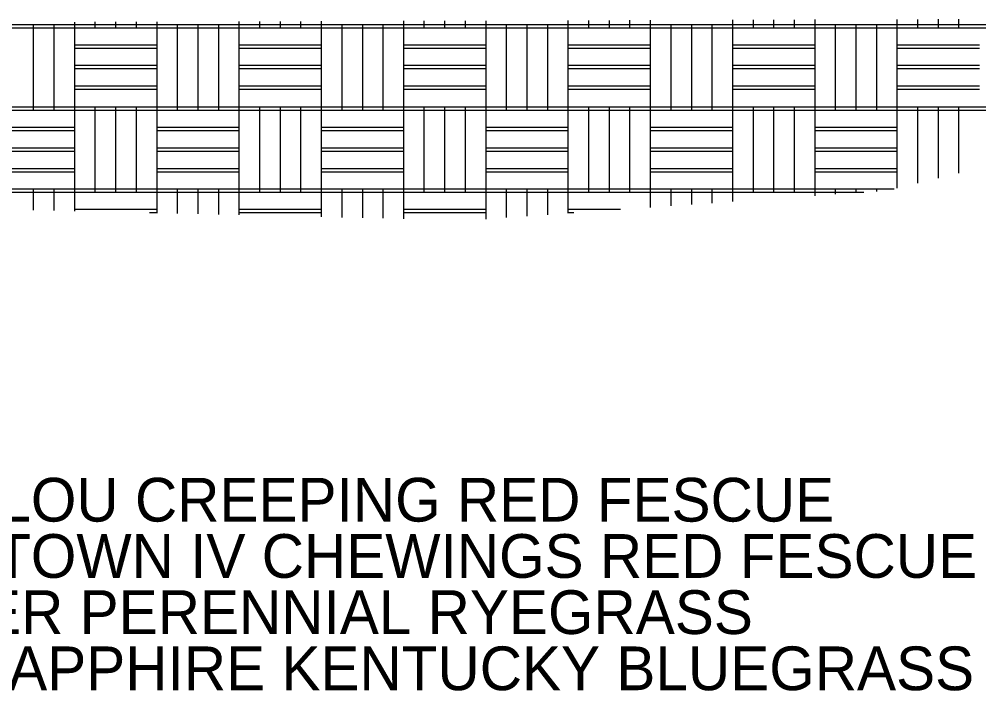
# Model space of a CAD drawing. Extents: x 9915.7 to 9955.7, y 9888.6 to 9936.3.
# Drawn here: x 9926.81 to 9942.16, y 9912.72 to 9923.46 of the extents above; entities that cross this region are included whole.
import ezdxf

# ---------------------------------------------------------------- set-up
doc = ezdxf.new("R2010")
doc.units = 0
for name, color, linetype in [('Default', 7, 'Continuous'), ('G-ANNO-TEXT', 7, 'Continuous'), ('G-DETL-PATT', 7, 'Continuous')]:
    doc.layers.add(name, color=color, linetype=linetype)

msp = doc.modelspace()

# ---------------------------------------------------------------- linework, layer by layer
at = {"layer": 'Default'}
for p, q in [((9936.91, 9923.05), (9935.594, 9923.05)), ((9939.541, 9923.05), (9938.225, 9923.05)), ((9942.172, 9923.05), (9940.856, 9923.05)), ((9935.684, 9920.366), (9935.594, 9920.366))]:
    msp.add_line(p, q, dxfattribs=at)
at = {"layer": 'G-DETL-PATT'}
for p, q in [((9922.786, 9923.379), (9943.064, 9923.379)), ((9922.826, 9923.326), (9943.06, 9923.326)), ((9927.044, 9922.063), (9927.044, 9923.379)), ((9927.044, 9922.01), (9927.044, 9923.326)), ((9927.373, 9922.063), (9927.373, 9923.379)), ((9927.373, 9922.01), (9927.373, 9923.326)), ((9927.702, 9923.379), (9927.702, 9923.419)), ((9927.702, 9923.326), (9927.702, 9923.419)), ((9927.702, 9922.063), (9927.702, 9923.379)), ((9927.702, 9922.01), (9927.702, 9923.326)), ((9928.03, 9923.379), (9928.03, 9923.42)), ((9928.03, 9923.326), (9928.03, 9923.42)), ((9928.359, 9923.379), (9928.359, 9923.421)), ((9928.359, 9923.326), (9928.359, 9923.421)), ((9928.688, 9923.379), (9928.688, 9923.422)), ((9928.688, 9923.326), (9928.688, 9923.422)), ((9929.017, 9923.379), (9929.017, 9923.423)), ((9929.017, 9923.326), (9929.017, 9923.423)), ((9929.017, 9922.063), (9929.017, 9923.379)), ((9929.017, 9922.01), (9929.017, 9923.326)), ((9929.346, 9922.063), (9929.346, 9923.379)), ((9929.346, 9922.01), (9929.346, 9923.326)), ((9929.675, 9922.063), (9929.675, 9923.379)), ((9929.675, 9922.01), (9929.675, 9923.326)), ((9930.004, 9922.063), (9930.004, 9923.379)), ((9930.004, 9922.01), (9930.004, 9923.326)), ((9930.332, 9923.379), (9930.332, 9923.427)), ((9930.332, 9923.326), (9930.332, 9923.427)), ((9930.332, 9922.063), (9930.332, 9923.379)), ((9930.332, 9922.01), (9930.332, 9923.326)), ((9930.661, 9923.379), (9930.661, 9923.428)), ((9930.661, 9923.326), (9930.661, 9923.428)), ((9930.99, 9923.379), (9930.99, 9923.429)), ((9930.99, 9923.326), (9930.99, 9923.429)), ((9931.319, 9923.379), (9931.319, 9923.43)), ((9931.319, 9923.326), (9931.319, 9923.43)), ((9931.648, 9923.379), (9931.648, 9923.431)), ((9931.648, 9923.326), (9931.648, 9923.431)), ((9931.648, 9922.063), (9931.648, 9923.379)), ((9931.648, 9922.01), (9931.648, 9923.326)), ((9931.977, 9922.063), (9931.977, 9923.379)), ((9931.977, 9922.01), (9931.977, 9923.326)), ((9932.306, 9922.063), (9932.306, 9923.379)), ((9932.306, 9922.01), (9932.306, 9923.326)), ((9932.635, 9922.063), (9932.635, 9923.379)), ((9932.635, 9922.01), (9932.635, 9923.326)), ((9932.963, 9923.379), (9932.963, 9923.436)), ((9932.963, 9923.326), (9932.963, 9923.436)), ((9932.963, 9922.063), (9932.963, 9923.379)), ((9932.963, 9922.01), (9932.963, 9923.326)), ((9933.292, 9923.379), (9933.292, 9923.437)), ((9933.292, 9923.326), (9933.292, 9923.437)), ((9933.621, 9923.379), (9933.621, 9923.438)), ((9933.621, 9923.326), (9933.621, 9923.438)), ((9933.95, 9923.379), (9933.95, 9923.439)), ((9933.95, 9923.326), (9933.95, 9923.439)), ((9934.279, 9923.379), (9934.279, 9923.44)), ((9934.279, 9923.326), (9934.279, 9923.44)), ((9934.279, 9922.063), (9934.279, 9923.379)), ((9934.279, 9922.01), (9934.279, 9923.326)), ((9934.608, 9922.063), (9934.608, 9923.379)), ((9934.608, 9922.01), (9934.608, 9923.326)), ((9934.937, 9922.063), (9934.937, 9923.379)), ((9934.937, 9922.01), (9934.937, 9923.326)), ((9935.266, 9922.063), (9935.266, 9923.379)), ((9935.266, 9922.01), (9935.266, 9923.326)), ((9935.594, 9923.379), (9935.594, 9923.444)), ((9935.594, 9923.326), (9935.594, 9923.444)), ((9935.594, 9922.063), (9935.594, 9923.379)), ((9935.594, 9922.01), (9935.594, 9923.326)), ((9935.923, 9923.379), (9935.923, 9923.445)), ((9935.923, 9923.326), (9935.923, 9923.445)), ((9936.252, 9923.379), (9936.252, 9923.446)), ((9936.252, 9923.326), (9936.252, 9923.446)), ((9936.581, 9923.379), (9936.581, 9923.447)), ((9936.581, 9923.326), (9936.581, 9923.447)), ((9936.91, 9923.379), (9936.91, 9923.449)), ((9936.91, 9923.326), (9936.91, 9923.449)), ((9936.91, 9922.063), (9936.91, 9923.379)), ((9936.91, 9922.01), (9936.91, 9923.326)), ((9937.239, 9922.063), (9937.239, 9923.379)), ((9937.239, 9922.01), (9937.239, 9923.326)), ((9937.568, 9922.063), (9937.568, 9923.379)), ((9937.568, 9922.01), (9937.568, 9923.326)), ((9937.896, 9922.063), (9937.896, 9923.379)), ((9937.896, 9922.01), (9937.896, 9923.326)), ((9938.225, 9923.379), (9938.225, 9923.453)), ((9938.225, 9923.326), (9938.225, 9923.453)), ((9938.225, 9922.063), (9938.225, 9923.379)), ((9938.225, 9922.01), (9938.225, 9923.326)), ((9938.554, 9923.379), (9938.554, 9923.454)), ((9938.554, 9923.326), (9938.554, 9923.454)), ((9938.883, 9923.379), (9938.883, 9923.455)), ((9938.883, 9923.326), (9938.883, 9923.455)), ((9939.212, 9923.379), (9939.212, 9923.456)), ((9939.212, 9923.326), (9939.212, 9923.456)), ((9939.541, 9923.379), (9939.541, 9923.457)), ((9939.541, 9923.326), (9939.541, 9923.457)), ((9939.541, 9922.063), (9939.541, 9923.379)), ((9939.541, 9922.01), (9939.541, 9923.326)), ((9939.87, 9922.063), (9939.87, 9923.379)), ((9939.87, 9922.01), (9939.87, 9923.326)), ((9940.199, 9922.063), (9940.199, 9923.379)), ((9940.199, 9922.01), (9940.199, 9923.326)), ((9940.527, 9922.063), (9940.527, 9923.379)), ((9940.527, 9922.01), (9940.527, 9923.326)), ((9940.856, 9923.379), (9940.856, 9923.461)), ((9940.856, 9923.326), (9940.856, 9923.461)), ((9940.856, 9922.063), (9940.856, 9923.379)), ((9940.856, 9922.01), (9940.856, 9923.326)), ((9941.185, 9923.379), (9941.185, 9923.462)), ((9941.185, 9923.326), (9941.185, 9923.462)), ((9941.514, 9923.379), (9941.514, 9923.463)), ((9941.514, 9923.326), (9941.514, 9923.463)), ((9941.843, 9923.379), (9941.843, 9923.465)), ((9941.843, 9923.326), (9941.843, 9923.465)), ((9929.017, 9923.05), (9927.702, 9923.05)), ((9931.648, 9923.05), (9930.332, 9923.05)), ((9934.279, 9923.05), (9932.963, 9923.05)), ((9929.017, 9922.997), (9927.702, 9922.997)), ((9931.648, 9922.997), (9930.332, 9922.997)), ((9934.279, 9922.997), (9932.963, 9922.997)), ((9936.91, 9922.997), (9935.594, 9922.997)), ((9939.541, 9922.997), (9938.225, 9922.997)), ((9942.172, 9922.997), (9940.856, 9922.997)), ((9929.017, 9922.721), (9927.702, 9922.721)), ((9931.648, 9922.721), (9930.332, 9922.721)), ((9934.279, 9922.721), (9932.963, 9922.721)), ((9936.91, 9922.721), (9935.594, 9922.721)), ((9939.541, 9922.721), (9938.225, 9922.721)), ((9942.172, 9922.721), (9940.856, 9922.721)), ((9929.017, 9922.668), (9927.702, 9922.668)), ((9931.648, 9922.668), (9930.332, 9922.668)), ((9934.279, 9922.668), (9932.963, 9922.668)), ((9936.91, 9922.668), (9935.594, 9922.668)), ((9939.541, 9922.668), (9938.225, 9922.668)), ((9942.172, 9922.668), (9940.856, 9922.668)), ((9929.017, 9922.392), (9927.702, 9922.392)), ((9929.017, 9922.339), (9927.702, 9922.339)), ((9931.648, 9922.392), (9930.332, 9922.392)), ((9931.648, 9922.339), (9930.332, 9922.339)), ((9934.279, 9922.392), (9932.963, 9922.392)), ((9934.279, 9922.339), (9932.963, 9922.339)), ((9936.91, 9922.392), (9935.594, 9922.392)), ((9936.91, 9922.339), (9935.594, 9922.339)), ((9939.541, 9922.392), (9938.225, 9922.392)), ((9939.541, 9922.339), (9938.225, 9922.339)), ((9942.172, 9922.392), (9940.856, 9922.392)), ((9942.172, 9922.339), (9940.856, 9922.339)), ((9923.791, 9922.063), (9942.892, 9922.063)), ((9923.831, 9922.01), (9942.882, 9922.01)), ((9926.386, 9922.063), (9927.702, 9922.063)), ((9926.386, 9922.01), (9927.702, 9922.01)), ((9927.702, 9920.748), (9927.702, 9922.063)), ((9927.702, 9920.695), (9927.702, 9922.01)), ((9928.03, 9920.748), (9928.03, 9922.063)), ((9928.03, 9920.695), (9928.03, 9922.01)), ((9928.359, 9920.748), (9928.359, 9922.063)), ((9928.359, 9920.695), (9928.359, 9922.01)), ((9928.688, 9920.748), (9928.688, 9922.063)), ((9928.688, 9920.695), (9928.688, 9922.01)), ((9929.017, 9920.748), (9929.017, 9922.063)), ((9929.017, 9922.063), (9930.332, 9922.063)), ((9929.017, 9920.695), (9929.017, 9922.01)), ((9929.017, 9922.01), (9930.332, 9922.01)), ((9930.332, 9920.748), (9930.332, 9922.063)), ((9930.332, 9920.695), (9930.332, 9922.01)), ((9930.661, 9920.748), (9930.661, 9922.063)), ((9930.661, 9920.695), (9930.661, 9922.01)), ((9930.99, 9920.748), (9930.99, 9922.063)), ((9930.99, 9920.695), (9930.99, 9922.01)), ((9931.319, 9920.748), (9931.319, 9922.063)), ((9931.319, 9920.695), (9931.319, 9922.01)), ((9931.648, 9920.748), (9931.648, 9922.063)), ((9931.648, 9922.063), (9932.963, 9922.063)), ((9931.648, 9920.695), (9931.648, 9922.01)), ((9931.648, 9922.01), (9932.963, 9922.01)), ((9932.963, 9920.748), (9932.963, 9922.063)), ((9932.963, 9920.695), (9932.963, 9922.01)), ((9933.292, 9920.748), (9933.292, 9922.063)), ((9933.292, 9920.695), (9933.292, 9922.01)), ((9933.621, 9920.748), (9933.621, 9922.063)), ((9933.621, 9920.695), (9933.621, 9922.01)), ((9933.95, 9920.748), (9933.95, 9922.063)), ((9933.95, 9920.695), (9933.95, 9922.01)), ((9934.279, 9920.748), (9934.279, 9922.063)), ((9934.279, 9922.063), (9935.594, 9922.063)), ((9934.279, 9920.695), (9934.279, 9922.01)), ((9934.279, 9922.01), (9935.594, 9922.01)), ((9935.594, 9920.748), (9935.594, 9922.063)), ((9935.594, 9920.695), (9935.594, 9922.01)), ((9935.923, 9920.748), (9935.923, 9922.063)), ((9935.923, 9920.695), (9935.923, 9922.01)), ((9936.252, 9920.748), (9936.252, 9922.063)), ((9936.252, 9920.695), (9936.252, 9922.01)), ((9936.581, 9920.748), (9936.581, 9922.063)), ((9936.581, 9920.695), (9936.581, 9922.01)), ((9936.91, 9920.748), (9936.91, 9922.063)), ((9936.91, 9922.063), (9938.225, 9922.063)), ((9936.91, 9920.695), (9936.91, 9922.01)), ((9936.91, 9922.01), (9938.225, 9922.01)), ((9938.225, 9920.748), (9938.225, 9922.063)), ((9938.225, 9920.695), (9938.225, 9922.01)), ((9938.554, 9920.748), (9938.554, 9922.063)), ((9938.554, 9920.695), (9938.554, 9922.01)), ((9938.883, 9920.748), (9938.883, 9922.063)), ((9938.883, 9920.695), (9938.883, 9922.01)), ((9939.212, 9920.748), (9939.212, 9922.063)), ((9939.212, 9920.695), (9939.212, 9922.01)), ((9939.541, 9920.748), (9939.541, 9922.063)), ((9939.541, 9922.063), (9940.856, 9922.063)), ((9939.541, 9920.695), (9939.541, 9922.01)), ((9939.541, 9922.01), (9940.856, 9922.01)), ((9940.856, 9920.76), (9940.856, 9922.063)), ((9940.856, 9920.76), (9940.856, 9922.01)), ((9941.185, 9920.84), (9941.185, 9922.063)), ((9941.185, 9920.84), (9941.185, 9922.01)), ((9941.514, 9920.919), (9941.514, 9922.063)), ((9941.514, 9920.919), (9941.514, 9922.01)), ((9941.843, 9920.999), (9941.843, 9922.063)), ((9941.843, 9920.999), (9941.843, 9922.01)), ((9926.386, 9921.734), (9927.702, 9921.734)), ((9926.386, 9921.681), (9927.702, 9921.681)), ((9929.017, 9921.734), (9930.332, 9921.734)), ((9929.017, 9921.681), (9930.332, 9921.681)), ((9931.648, 9921.734), (9932.963, 9921.734)), ((9931.648, 9921.681), (9932.963, 9921.681)), ((9934.279, 9921.734), (9935.594, 9921.734)), ((9934.279, 9921.681), (9935.594, 9921.681)), ((9936.91, 9921.734), (9938.225, 9921.734)), ((9936.91, 9921.681), (9938.225, 9921.681)), ((9939.541, 9921.734), (9940.856, 9921.734)), ((9939.541, 9921.681), (9940.856, 9921.681)), ((9926.386, 9921.405), (9927.702, 9921.405)), ((9926.386, 9921.353), (9927.702, 9921.353)), ((9929.017, 9921.405), (9930.332, 9921.405)), ((9929.017, 9921.353), (9930.332, 9921.353)), ((9931.648, 9921.405), (9932.963, 9921.405)), ((9931.648, 9921.353), (9932.963, 9921.353)), ((9934.279, 9921.405), (9935.594, 9921.405)), ((9934.279, 9921.353), (9935.594, 9921.353)), ((9936.91, 9921.405), (9938.225, 9921.405)), ((9936.91, 9921.353), (9938.225, 9921.353)), ((9939.541, 9921.405), (9940.856, 9921.405)), ((9939.541, 9921.353), (9940.856, 9921.353)), ((9926.386, 9921.077), (9927.702, 9921.077)), ((9926.386, 9921.024), (9927.702, 9921.024)), ((9929.017, 9921.077), (9930.332, 9921.077)), ((9929.017, 9921.024), (9930.332, 9921.024)), ((9931.648, 9921.077), (9932.963, 9921.077)), ((9931.648, 9921.024), (9932.963, 9921.024)), ((9934.279, 9921.077), (9935.594, 9921.077)), ((9934.279, 9921.024), (9935.594, 9921.024)), ((9936.91, 9921.077), (9938.225, 9921.077)), ((9936.91, 9921.024), (9938.225, 9921.024)), ((9939.541, 9921.077), (9940.856, 9921.077)), ((9939.541, 9921.024), (9940.856, 9921.024)), ((9924.796, 9920.748), (9940.805, 9920.748)), ((9927.044, 9920.41), (9927.044, 9920.748)), ((9927.373, 9920.402), (9927.373, 9920.748)), ((9927.702, 9920.394), (9927.702, 9920.748)), ((9929.017, 9920.363), (9929.017, 9920.748)), ((9929.346, 9920.355), (9929.346, 9920.748)), ((9929.675, 9920.348), (9929.675, 9920.748)), ((9930.004, 9920.34), (9930.004, 9920.748)), ((9930.332, 9920.332), (9930.332, 9920.748)), ((9931.648, 9920.301), (9931.648, 9920.748)), ((9931.977, 9920.293), (9931.977, 9920.748)), ((9932.306, 9920.286), (9932.306, 9920.748)), ((9932.635, 9920.278), (9932.635, 9920.748)), ((9932.963, 9920.27), (9932.963, 9920.748)), ((9934.279, 9920.266), (9934.279, 9920.748)), ((9934.608, 9920.29), (9934.608, 9920.748)), ((9934.937, 9920.313), (9934.937, 9920.748)), ((9935.266, 9920.336), (9935.266, 9920.748)), ((9935.594, 9920.36), (9935.594, 9920.748)), ((9936.91, 9920.453), (9936.91, 9920.748)), ((9937.239, 9920.476), (9937.239, 9920.748)), ((9937.568, 9920.5), (9937.568, 9920.748)), ((9937.896, 9920.523), (9937.896, 9920.748)), ((9938.225, 9920.546), (9938.225, 9920.748)), ((9939.541, 9920.64), (9939.541, 9920.748)), ((9939.87, 9920.663), (9939.87, 9920.748)), ((9940.199, 9920.686), (9940.199, 9920.748)), ((9940.527, 9920.709), (9940.527, 9920.748)), ((9924.836, 9920.695), (9940.321, 9920.695)), ((9927.044, 9920.41), (9927.044, 9920.695)), ((9927.373, 9920.402), (9927.373, 9920.695)), ((9927.702, 9920.394), (9927.702, 9920.695)), ((9929.017, 9920.363), (9929.017, 9920.695)), ((9929.346, 9920.355), (9929.346, 9920.695)), ((9929.675, 9920.348), (9929.675, 9920.695)), ((9930.004, 9920.34), (9930.004, 9920.695)), ((9930.332, 9920.332), (9930.332, 9920.695)), ((9931.648, 9920.301), (9931.648, 9920.695)), ((9931.977, 9920.293), (9931.977, 9920.695)), ((9932.306, 9920.286), (9932.306, 9920.695)), ((9932.635, 9920.278), (9932.635, 9920.695)), ((9932.963, 9920.27), (9932.963, 9920.695)), ((9934.279, 9920.266), (9934.279, 9920.695)), ((9934.608, 9920.29), (9934.608, 9920.695)), ((9934.937, 9920.313), (9934.937, 9920.695)), ((9935.266, 9920.336), (9935.266, 9920.695)), ((9935.594, 9920.36), (9935.594, 9920.695)), ((9936.91, 9920.453), (9936.91, 9920.695)), ((9937.239, 9920.476), (9937.239, 9920.695)), ((9937.568, 9920.5), (9937.568, 9920.695)), ((9937.896, 9920.523), (9937.896, 9920.695)), ((9938.225, 9920.546), (9938.225, 9920.695)), ((9939.541, 9920.64), (9939.541, 9920.695)), ((9939.87, 9920.663), (9939.87, 9920.695)), ((9940.199, 9920.686), (9940.199, 9920.695)), ((9929.017, 9920.419), (9927.702, 9920.419)), ((9931.648, 9920.419), (9930.332, 9920.419)), ((9934.279, 9920.419), (9932.963, 9920.419)), ((9936.429, 9920.419), (9935.594, 9920.419)), ((9929.017, 9920.366), (9928.895, 9920.366)), ((9931.648, 9920.366), (9930.332, 9920.366)), ((9934.279, 9920.366), (9932.963, 9920.366))]:
    msp.add_line(p, q, dxfattribs=at)

# ---------------------------------------------------------------- texts
at = {"layer": 'G-ANNO-TEXT'}
for s, p in [('35% CINDY LOU CREEPING RED FESCUE', (9921.173, 9915.425)), ('20% JAMESTOWN IV CHEWINGS RED FESCUE', (9921.173, 9914.525)), ('25% CRUISER PERENNIAL RYEGRASS', (9921.173, 9913.626)), ('10% BLUE SAPPHIRE KENTUCKY BLUEGRASS', (9921.173, 9912.727))]:
    msp.add_text(s, height=0.7, dxfattribs=at).set_placement(p)

doc.saveas('drawing.dxf')
